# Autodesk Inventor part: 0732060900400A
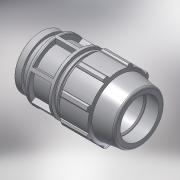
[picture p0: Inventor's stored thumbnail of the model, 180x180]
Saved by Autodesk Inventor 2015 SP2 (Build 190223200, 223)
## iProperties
Created: 2017-02
Part Number: 0732060900400A
Material: PVC-Piping
Description: PLASSON SHOULDERED ADAPTOR 90-4"
Document SubType Name: Modeling
Designer: KIM
Mass: 92.6774 g
Surface Area: 199.44 cm^2
Volume: 66.1981 cm^3
Density: 1.4 g/cm^3
Appearance: Smooth - White
Author: KIM
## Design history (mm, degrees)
derived "87320.ipt"
feature "Solid1::87320.ipt"
tag "TaggingFeature1"
body "Solid1"
other parameters: "d4" = 33, "d5" = 46.2, "d7" = 154, "d8" = 115.5, "d9" = 33, "d11" = 8.25, "d12" = 123.2, "d13" = 120 deg, "d14" = 117, "d15" = 8 deg, "d16" = 138.6, "d18" = 4.5, "d19" = 35 deg, "d20" = 17.5 deg, "d21" = 143.22, "d23" = 0, "d25" = 360 deg, "d27" = 3.08, "d34" = 7.7, "d36" = 0, "d42" = 69.3, "d43" = 4.62, "d46" = 2.7, "d51" = 231, "d53" = 1.8, "d55" = 360 deg, "d57" = 123, "d59" = 46.2, "d61" = 110.7, "d62" = 16, "d64" = 5.2, "d66" = 131.67, "d67" = 5.2, "d70" = 86.1, "d71" = 73.8, "d73" = 6.15, "d74" = 16, "E_" = 154, "H_" = 231, "L_" = 16, "B_" = 123, "d63" = 20.8, "d72" = 18.45
